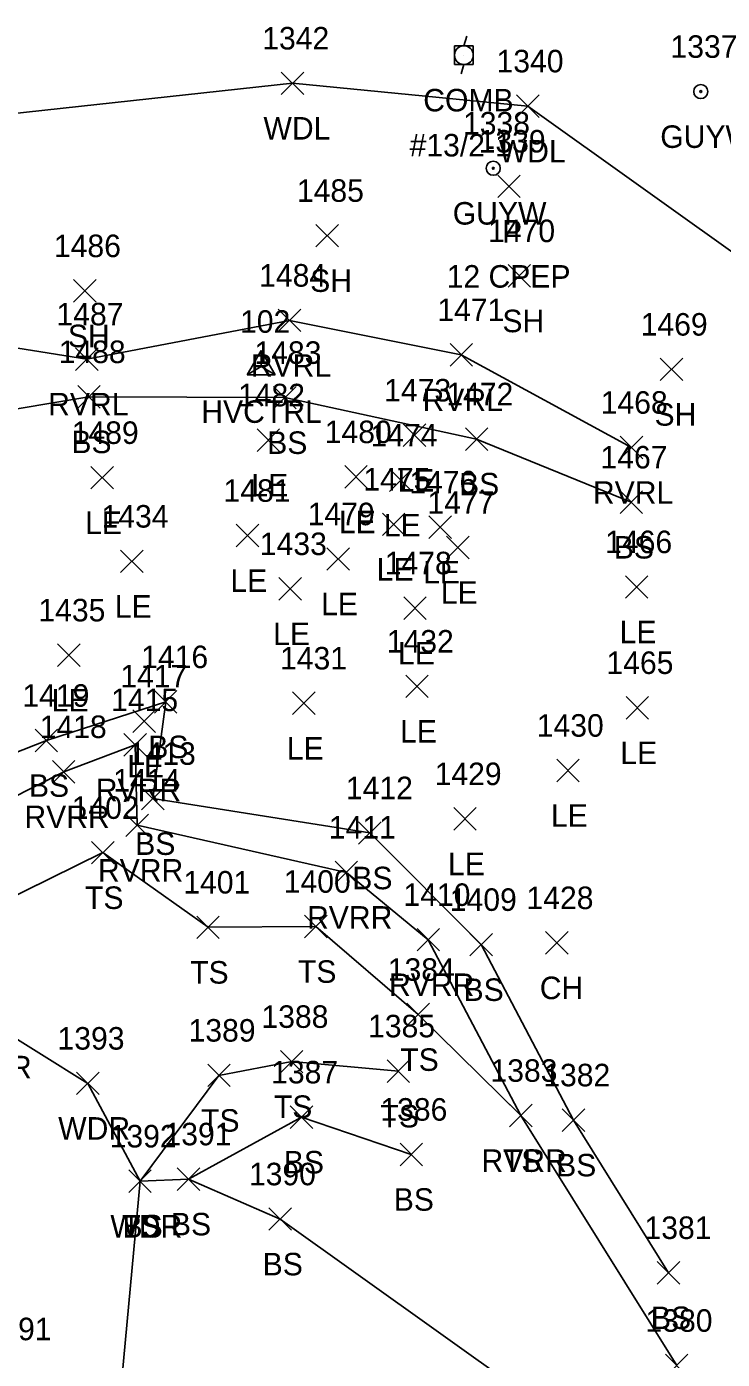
# Model space of a CAD drawing. Extents: x 1620157 to 1620595, y 115111 to 117885.
# Drawn here: x 1620392.2 to 1620454, y 115358.6 to 115476.9 of the extents above; entities that cross this region are included whole.
import ezdxf

# ---------------------------------------------------------------- set-up
doc = ezdxf.new("R2010")
doc.units = 0
for name, color, linetype in [('C_A', 7, 'Continuous'), ('C_I', 7, 'Continuous'), ('CPSM', 7, 'Continuous'), ('D_A', 7, 'Continuous'), ('D_C', 7, 'Continuous'), ('D_I', 7, 'Continuous'), ('D_TIC', 7, 'Continuous'), ('L_A', 7, 'Continuous'), ('L_I', 7, 'Continuous'), ('L_TIC', 7, 'Continuous'), ('LAWA', 7, 'Continuous'), ('LAWE', 7, 'Continuous'), ('LELB', 7, 'Continuous'), ('U_A', 7, 'Continuous'), ('U_C', 7, 'Continuous'), ('U_I', 7, 'Continuous'), ('UP', 7, 'Continuous'), ('UPGW', 7, 'Continuous')]:
    doc.layers.add(name, color=color, linetype=linetype)

msp = doc.modelspace()

# ---------------------------------------------------------------- linework, layer by layer
at = {"layer": 'CPSM'}
for p, q in [((1620411.8, 115446.03), (1620413.05, 115448.19)), ((1620414.3, 115446.03), (1620413.05, 115448.19)), ((1620413.05, 115446.75), (1620413.05, 115448.19)), ((1620411.8, 115446.03), (1620413.05, 115446.75)), ((1620411.8, 115446.03), (1620414.3, 115446.03)), ((1620413.05, 115446.75), (1620413.05, 115446.75)), ((1620413.05, 115446.75), (1620414.3, 115446.03))]:
    msp.add_line(p, q, dxfattribs=at)
at = {"layer": 'D_TIC'}
for points in [[(1620434.07, 115461.76), (1620436.07, 115463.76)], [(1620436.07, 115461.76), (1620434.07, 115463.76)]]:
    msp.add_lwpolyline(points, dxfattribs=at)
at = {"layer": 'L_TIC'}
for points in [[(1620414.84, 115470.91), (1620416.84, 115472.91)], [(1620416.84, 115470.91), (1620414.84, 115472.91)], [(1620435.74, 115468.88), (1620437.74, 115470.88)], [(1620437.74, 115468.88), (1620435.74, 115470.88)], [(1620417.92, 115457.38), (1620419.92, 115459.38)], [(1620419.92, 115457.38), (1620417.92, 115459.38)], [(1620434.99, 115453.8), (1620436.99, 115455.8)], [(1620436.99, 115453.8), (1620434.99, 115455.8)], [(1620396.4, 115452.47), (1620398.4, 115454.47)], [(1620398.4, 115452.47), (1620396.4, 115454.47)], [(1620414.58, 115449.85), (1620416.58, 115451.85)], [(1620416.58, 115449.85), (1620414.58, 115451.85)], [(1620396.57, 115446.41), (1620398.57, 115448.41)], [(1620398.57, 115446.41), (1620396.57, 115448.41)], [(1620429.83, 115446.79), (1620431.83, 115448.79)], [(1620431.83, 115446.79), (1620429.83, 115448.79)], [(1620448.5, 115445.5), (1620450.5, 115447.5)], [(1620450.5, 115445.5), (1620448.5, 115447.5)], [(1620396.76, 115443.06), (1620398.76, 115445.06)], [(1620398.76, 115443.06), (1620396.76, 115445.06)], [(1620414.15, 115442.99), (1620416.15, 115444.99)], [(1620416.15, 115442.99), (1620414.15, 115444.99)], [(1620412.69, 115439.22), (1620414.69, 115441.22)], [(1620414.69, 115439.22), (1620412.69, 115441.22)], [(1620425.67, 115439.65), (1620427.67, 115441.65)], [(1620427.67, 115439.65), (1620425.67, 115441.65)], [(1620431.19, 115439.31), (1620433.19, 115441.31)], [(1620433.19, 115439.31), (1620431.19, 115441.31)], [(1620444.95, 115438.56), (1620446.95, 115440.56)], [(1620446.95, 115438.56), (1620444.95, 115440.56)], [(1620397.93, 115435.88), (1620399.93, 115437.88)], [(1620399.93, 115435.88), (1620397.93, 115437.88)], [(1620420.48, 115435.95), (1620422.48, 115437.95)], [(1620422.48, 115435.95), (1620420.48, 115437.95)], [(1620424.46, 115435.66), (1620426.46, 115437.66)], [(1620426.46, 115435.66), (1620424.46, 115437.66)], [(1620444.93, 115433.7), (1620446.93, 115435.7)], [(1620446.93, 115433.7), (1620444.93, 115435.7)], [(1620410.84, 115430.74), (1620412.84, 115432.74)], [(1620412.84, 115430.74), (1620410.84, 115432.74)], [(1620423.82, 115431.74), (1620425.82, 115433.74)], [(1620425.82, 115431.74), (1620423.82, 115433.74)], [(1620427.95, 115431.49), (1620429.95, 115433.49)], [(1620429.95, 115431.49), (1620427.95, 115433.49)], [(1620429.52, 115429.68), (1620431.52, 115431.68)], [(1620431.52, 115429.68), (1620429.52, 115431.68)], [(1620400.57, 115428.45), (1620402.57, 115430.45)], [(1620402.57, 115428.45), (1620400.57, 115430.45)], [(1620418.89, 115428.66), (1620420.89, 115430.66)], [(1620420.89, 115428.66), (1620418.89, 115430.66)], [(1620414.63, 115426.01), (1620416.63, 115428.01)], [(1620416.63, 115426.01), (1620414.63, 115428.01)], [(1620445.4, 115426.18), (1620447.4, 115428.18)], [(1620447.4, 115426.18), (1620445.4, 115428.18)], [(1620425.72, 115424.3), (1620427.72, 115426.3)], [(1620427.72, 115424.3), (1620425.72, 115426.3)], [(1620394.97, 115420.12), (1620396.97, 115422.12)], [(1620396.97, 115420.12), (1620394.97, 115422.12)], [(1620425.9, 115417.35), (1620427.9, 115419.35)], [(1620427.9, 115417.35), (1620425.9, 115419.35)], [(1620403.58, 115415.97), (1620405.58, 115417.97)], [(1620405.58, 115415.97), (1620403.58, 115417.97)], [(1620415.85, 115415.85), (1620417.85, 115417.85)], [(1620417.85, 115415.85), (1620415.85, 115417.85)], [(1620445.46, 115415.45), (1620447.46, 115417.45)], [(1620447.46, 115415.45), (1620445.46, 115417.45)], [(1620401.67, 115414.26), (1620403.67, 115416.26)], [(1620403.67, 115414.26), (1620401.67, 115416.26)], [(1620392.98, 115412.54), (1620394.98, 115414.54)], [(1620394.98, 115412.54), (1620392.98, 115414.54)], [(1620400.86, 115412.15), (1620402.86, 115414.15)], [(1620402.86, 115412.15), (1620400.86, 115414.15)], [(1620394.52, 115409.76), (1620396.52, 115411.76)], [(1620396.52, 115409.76), (1620394.52, 115411.76)], [(1620439.31, 115409.88), (1620441.31, 115411.88)], [(1620441.31, 115409.88), (1620439.31, 115411.88)], [(1620402.43, 115407.38), (1620404.43, 115409.38)], [(1620404.43, 115407.38), (1620402.43, 115409.38)], [(1620401.04, 115405.01), (1620403.04, 115407.01)], [(1620403.04, 115405.01), (1620401.04, 115407.01)], [(1620430.16, 115405.58), (1620432.16, 115407.58)], [(1620432.16, 115405.58), (1620430.16, 115407.58)], [(1620421.71, 115404.33), (1620423.71, 115406.33)], [(1620423.71, 115404.33), (1620421.71, 115406.33)], [(1620398, 115402.58), (1620400, 115404.58)], [(1620400, 115402.58), (1620398, 115404.58)], [(1620419.62, 115400.83), (1620421.62, 115402.83)], [(1620421.62, 115400.83), (1620419.62, 115402.83)], [(1620407.34, 115395.95), (1620409.34, 115397.95)], [(1620409.34, 115395.95), (1620407.34, 115397.95)], [(1620416.91, 115396.02), (1620418.91, 115398.02)], [(1620418.91, 115396.02), (1620416.91, 115398.02)], [(1620426.9, 115394.85), (1620428.9, 115396.85)], [(1620428.9, 115394.85), (1620426.9, 115396.85)], [(1620431.59, 115394.41), (1620433.59, 115396.41)], [(1620433.59, 115394.41), (1620431.59, 115396.41)], [(1620431.59, 115394.41), (1620433.59, 115396.41)], [(1620433.59, 115394.41), (1620431.59, 115396.41)], [(1620438.31, 115394.57), (1620440.31, 115396.57)], [(1620440.31, 115394.57), (1620438.31, 115396.57)], [(1620426, 115388.2), (1620428, 115390.2)], [(1620428, 115388.2), (1620426, 115390.2)], [(1620414.77, 115384.02), (1620416.77, 115386.02)], [(1620416.77, 115384.02), (1620414.77, 115386.02)], [(1620396.67, 115382.09), (1620398.67, 115384.09)], [(1620398.67, 115382.09), (1620396.67, 115384.09)], [(1620408.31, 115382.8), (1620410.31, 115384.8)], [(1620410.31, 115382.8), (1620408.31, 115384.8)], [(1620424.24, 115383.18), (1620426.24, 115385.18)], [(1620426.24, 115383.18), (1620424.24, 115385.18)], [(1620415.63, 115379.09), (1620417.63, 115381.09)], [(1620417.63, 115379.09), (1620415.63, 115381.09)], [(1620435.11, 115379.23), (1620437.11, 115381.23)], [(1620437.11, 115379.23), (1620435.11, 115381.23)], [(1620435.11, 115379.23), (1620437.11, 115381.23)], [(1620437.11, 115379.23), (1620435.11, 115381.23)], [(1620439.8, 115378.83), (1620441.8, 115380.83)], [(1620441.8, 115378.83), (1620439.8, 115380.83)], [(1620425.39, 115375.78), (1620427.39, 115377.78)], [(1620427.39, 115375.78), (1620425.39, 115377.78)], [(1620401.3, 115373.4), (1620403.3, 115375.4)], [(1620403.3, 115373.4), (1620401.3, 115375.4)], [(1620401.3, 115373.4), (1620403.3, 115375.4)], [(1620403.3, 115373.4), (1620401.3, 115375.4)], [(1620401.3, 115373.4), (1620403.3, 115375.4)], [(1620403.3, 115373.4), (1620401.3, 115375.4)], [(1620405.6, 115373.59), (1620407.6, 115375.59)], [(1620407.6, 115373.59), (1620405.6, 115375.59)], [(1620405.6, 115373.59), (1620407.6, 115375.59)], [(1620407.6, 115373.59), (1620405.6, 115375.59)], [(1620413.75, 115370.04), (1620415.75, 115372.04)], [(1620415.75, 115370.04), (1620413.75, 115372.04)], [(1620448.23, 115365.27), (1620450.23, 115367.27)], [(1620450.23, 115365.27), (1620448.23, 115367.27)], [(1620448.96, 115357.03), (1620450.96, 115359.03)], [(1620450.96, 115357.03), (1620448.96, 115359.03)]]:
    msp.add_lwpolyline(points, dxfattribs=at)
at = {"layer": 'LAWA'}
for points in [[(1620457.22, 115455.24), (1620436.74, 115469.88), (1620415.84, 115471.91), (1620388.94, 115469), (1620365.7, 115463.66), (1620354.53, 115463.4)], [(1620479.84, 115302.47), (1620458.1, 115310.32), (1620439.1, 115318.77), (1620415.16, 115330.85), (1620411.08, 115337.59), (1620399.96, 115349.14), (1620402.3, 115374.4), (1620397.67, 115383.09), (1620388.93, 115388.54), (1620379.18, 115389.78), (1620376.07, 115393.24)]]:
    msp.add_lwpolyline(points, dxfattribs=at)
at = {"layer": 'LAWE'}
for points in [[(1620445.95, 115439.56), (1620430.83, 115447.79), (1620415.58, 115450.85), (1620397.57, 115447.41), (1620383.81, 115449.59), (1620366.25, 115449.84), (1620353.62, 115446.61), (1620348.79, 115438.68), (1620343.85, 115441.04)], [(1620449.96, 115358.03), (1620436.11, 115380.23), (1620427.9, 115395.85), (1620420.62, 115401.83), (1620402.04, 115406.01), (1620401.86, 115413.15), (1620395.52, 115410.76), (1620383.17, 115404.52), (1620364.02, 115400.22), (1620359.48, 115398.99)]]:
    msp.add_lwpolyline(points, dxfattribs=at)
at = {"layer": 'LELB'}
for points in [[(1620445.93, 115434.7), (1620432.19, 115440.31), (1620415.15, 115443.99), (1620397.76, 115444.06), (1620388.34, 115442.49), (1620368.19, 115442.37), (1620354.52, 115441.05), (1620350.88, 115433.96), (1620346.48, 115432.5), (1620338.97, 115434.36), (1620325.33, 115430.43), (1620316.03, 115427.32), (1620308.72, 115416.91), (1620294.48, 115412.65), (1620281.32, 115408.44), (1620263.96, 115399.24), (1620237.91, 115391.7), (1620225.01, 115391.23), (1620212.86, 115385.97)], [(1620432.59, 115395.41), (1620422.71, 115405.33), (1620403.43, 115408.38), (1620404.58, 115416.97), (1620393.98, 115413.54), (1620383.75, 115409.51), (1620371.98, 115408.92), (1620364.43, 115404.02)], [(1620436.11, 115380.23), (1620427, 115389.2), (1620417.91, 115397.02), (1620408.34, 115396.95), (1620399, 115403.58), (1620387.34, 115397.86), (1620376.07, 115393.24), (1620369.35, 115391.41)], [(1620449.23, 115366.27), (1620440.8, 115379.83), (1620432.59, 115395.41)], [(1620425.24, 115384.18), (1620415.77, 115385.02), (1620409.31, 115383.8), (1620402.3, 115374.4)], [(1620426.39, 115376.78), (1620416.63, 115380.09), (1620406.6, 115374.59)], [(1620450.2, 115345.73), (1620414.75, 115371.04), (1620406.6, 115374.59), (1620402.3, 115374.4)]]:
    msp.add_lwpolyline(points, dxfattribs=at)
at = {"layer": 'UP'}
for p, q in [((1620430.23, 115473.58), (1620430.23, 115475.24)), ((1620430.23, 115475.24), (1620431.89, 115475.24)), ((1620431.31, 115476.08), (1620431.06, 115475.24)), ((1620431.89, 115475.24), (1620431.89, 115473.58)), ((1620431.06, 115474.41), (1620431.06, 115474.41)), ((1620431.89, 115473.58), (1620430.23, 115473.58)), ((1620430.81, 115472.74), (1620431.06, 115473.58))]:
    msp.add_line(p, q, dxfattribs=at)
msp.add_circle((1620431.06, 115474.41), 0.833, dxfattribs=at)
at = {"layer": 'UPGW'}
for centre, radius in [((1620452.1, 115471.17), 0.625), ((1620452.1, 115471.17), 0.0833), ((1620433.67, 115464.36), 0.625), ((1620433.67, 115464.36), 0.0833)]:
    msp.add_circle(centre, radius, dxfattribs=at)

# ---------------------------------------------------------------- texts
at = {"layer": 'C_A'}
msp.add_text('HVCTRL', height=2, dxfattribs=at).set_placement((1620407.74, 115441.75))
at = {"layer": 'C_I'}
msp.add_text('102', height=2, dxfattribs=at).set_placement((1620411.18, 115449.75))
at = {"layer": 'D_A'}
msp.add_text('P', height=2, dxfattribs=at).set_placement((1620434.45, 115457.76))
at = {"layer": 'D_C'}
msp.add_text('12 CPEP', height=2, dxfattribs=at).set_placement((1620429.53, 115453.76))
at = {"layer": 'D_I'}
msp.add_text('1339', height=2, dxfattribs=at).set_placement((1620432.37, 115465.76))
at = {"layer": 'L_A'}
for s, p in [('WDL', (1620413.26, 115466.91)), ('WDL', (1620434.16, 115464.88)), ('SH', (1620417.41, 115453.38)), ('SH', (1620434.48, 115449.8)), ('SH', (1620395.89, 115448.47)), ('RVRL', (1620412.14, 115445.85)), ('RVRL', (1620427.39, 115442.79)), ('RVRL', (1620394.14, 115442.41)), ('SH', (1620447.99, 115441.5)), ('BS', (1620396.2, 115439.06)), ('BS', (1620413.59, 115438.99)), ('LE', (1620425.16, 115435.65)), ('BS', (1620430.63, 115435.31)), ('LE', (1620412.18, 115435.22)), ('RVRL', (1620442.52, 115434.56)), ('LE', (1620397.42, 115431.88)), ('LE', (1620419.96, 115431.95)), ('LE', (1620423.95, 115431.66)), ('BS', (1620444.37, 115429.7)), ('LE', (1620423.31, 115427.74)), ('LE', (1620427.44, 115427.49)), ('LE', (1620410.32, 115426.74)), ('LE', (1620429.01, 115425.68)), ('LE', (1620400.06, 115424.45)), ('LE', (1620418.38, 115424.66)), ('LE', (1620414.12, 115422.01)), ('LE', (1620444.89, 115422.18)), ('LE', (1620425.21, 115420.3)), ('LE', (1620394.45, 115416.12)), ('LE', (1620425.39, 115413.35)), ('BS', (1620403.03, 115411.97)), ('LE', (1620415.34, 115411.85)), ('LE', (1620444.95, 115411.45)), ('LE', (1620401.16, 115410.26)), ('BS', (1620392.43, 115408.54)), ('RVRR', (1620398.37, 115408.15)), ('RVRR', (1620392.03, 115405.76)), ('LE', (1620438.79, 115405.88)), ('BS', (1620401.87, 115403.38)), ('RVRR', (1620398.56, 115401.01)), ('LE', (1620429.65, 115401.58)), ('BS', (1620421.15, 115400.33)), ('TS', (1620397.41, 115398.58)), ('RVRR', (1620417.13, 115396.83)), ('TS', (1620406.75, 115391.95)), ('TS', (1620416.32, 115392.02)), ('RVRR', (1620424.41, 115390.85)), ('BS', (1620431.03, 115390.41)), ('BS', (1620431.03, 115390.41)), ('CH', (1620437.8, 115390.57)), ('WDR', (1620386.29, 115383.54)), ('TS', (1620425.41, 115384.2)), ('TS', (1620414.18, 115380.02)), ('TS', (1620407.72, 115378.8)), ('TS', (1620423.65, 115379.18)), ('WDR', (1620395.03, 115378.09)), ('BS', (1620415.07, 115375.09)), ('RVRR', (1620432.62, 115375.23)), ('TS', (1620434.52, 115375.23)), ('BS', (1620439.25, 115374.83)), ('BS', (1620424.83, 115371.78)), ('WDR', (1620399.66, 115369.4)), ('TS', (1620400.71, 115369.4)), ('BS', (1620400.74, 115369.4)), ('BS', (1620405.04, 115369.59)), ('BS', (1620405.04, 115369.59)), ('BS', (1620413.19, 115366.04)), ('BS', (1620447.67, 115361.27))]:
    msp.add_text(s, height=2, dxfattribs=at).set_placement(p)
at = {"layer": 'L_I'}
for s, p in [('1342', (1620413.15, 115474.91)), ('1340', (1620433.96, 115472.88)), ('1485', (1620416.23, 115461.38)), ('1470', (1620433.21, 115457.8)), ('1486', (1620394.65, 115456.47)), ('1484', (1620412.88, 115453.85)), ('1471', (1620428.7, 115450.79)), ('1487', (1620394.88, 115450.41)), ('1469', (1620446.76, 115449.5)), ('1488', (1620395.07, 115447.06)), ('1483', (1620412.46, 115446.99)), ('1473', (1620423.98, 115443.65)), ('1482', (1620411, 115443.22)), ('1472', (1620429.5, 115443.31)), ('1468', (1620443.21, 115442.56)), ('1489', (1620396.23, 115439.88)), ('1480', (1620418.7, 115439.95)), ('1474', (1620422.77, 115439.66)), ('1467', (1620443.19, 115437.7)), ('1475', (1620422.13, 115435.74)), ('1476', (1620426.21, 115435.49)), ('1481', (1620409.71, 115434.74)), ('1477', (1620427.83, 115433.68)), ('1434', (1620398.88, 115432.45)), ('1479', (1620417.19, 115432.66)), ('1433', (1620412.94, 115430.01)), ('1466', (1620443.61, 115430.18)), ('1478', (1620424.03, 115428.3)), ('1435', (1620393.27, 115424.12)), ('1432', (1620424.21, 115421.35)), ('1416', (1620402.4, 115419.97)), ('1431', (1620414.73, 115419.85)), ('1465', (1620443.72, 115419.45)), ('1417', (1620400.55, 115418.26)), ('1419', (1620391.85, 115416.54)), ('1415', (1620399.73, 115416.15)), ('1418', (1620393.39, 115413.76)), ('1430', (1620437.53, 115413.88)), ('1413', (1620401.3, 115411.38)), ('1429', (1620428.46, 115409.58)), ('1414', (1620399.92, 115409.01)), ('1412', (1620420.58, 115408.33)), ('1402', (1620396.23, 115406.58)), ('1411', (1620419.06, 115404.83)), ('1401', (1620406.14, 115399.95)), ('1400', (1620415.06, 115400.02)), ('1410', (1620425.69, 115398.85)), ('1409', (1620429.81, 115398.41)), ('1409', (1620429.81, 115398.41)), ('1428', (1620436.62, 115398.57)), ('1384', (1620424.3, 115392.2)), ('1388', (1620413.08, 115388.02)), ('1389', (1620406.61, 115386.8)), ('1385', (1620422.55, 115387.18)), ('1393', (1620394.97, 115386.09)), ('1383', (1620433.42, 115383.23)), ('1383', (1620433.42, 115383.23)), ('1387', (1620413.94, 115383.09)), ('1382', (1620438.11, 115382.83)), ('1386', (1620423.64, 115379.78)), ('1392', (1620399.6, 115377.4)), ('1392', (1620399.6, 115377.4)), ('1392', (1620399.6, 115377.4)), ('1391', (1620404.47, 115377.59)), ('1391', (1620404.47, 115377.59)), ('1390', (1620411.97, 115374.04)), ('1381', (1620447.1, 115369.27)), ('1380', (1620447.19, 115361.03)), ('1291', (1620388.49, 115360.28))]:
    msp.add_text(s, height=2, dxfattribs=at).set_placement(p)
at = {"layer": 'U_A'}
for s, p in [('COMB', (1620427.45, 115469.41)), ('GUYW', (1620448.5, 115466.17)), ('GUYW', (1620430.07, 115459.36))]:
    msp.add_text(s, height=2, dxfattribs=at).set_placement(p)
at = {"layer": 'U_C'}
msp.add_text('#13/2-1', height=2, dxfattribs=at).set_placement((1620426.24, 115465.41))
at = {"layer": 'U_I'}
for s, p in [('1337', (1620449.41, 115474.17)), ('1338', (1620430.98, 115467.36))]:
    msp.add_text(s, height=2, dxfattribs=at).set_placement(p)

doc.saveas('drawing.dxf')
